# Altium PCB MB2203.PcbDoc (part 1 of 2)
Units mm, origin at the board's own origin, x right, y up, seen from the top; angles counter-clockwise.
Board outline 43 x 31 mm, 4 copper layers (Top Layer, Signal Layer 1, Signal Layer 2, Bottom Layer), stack 0.599 mm thick; 49 components, 37 nets, 166 pads, 723 vias.
Unrouted connection lines stored in the file: 92.
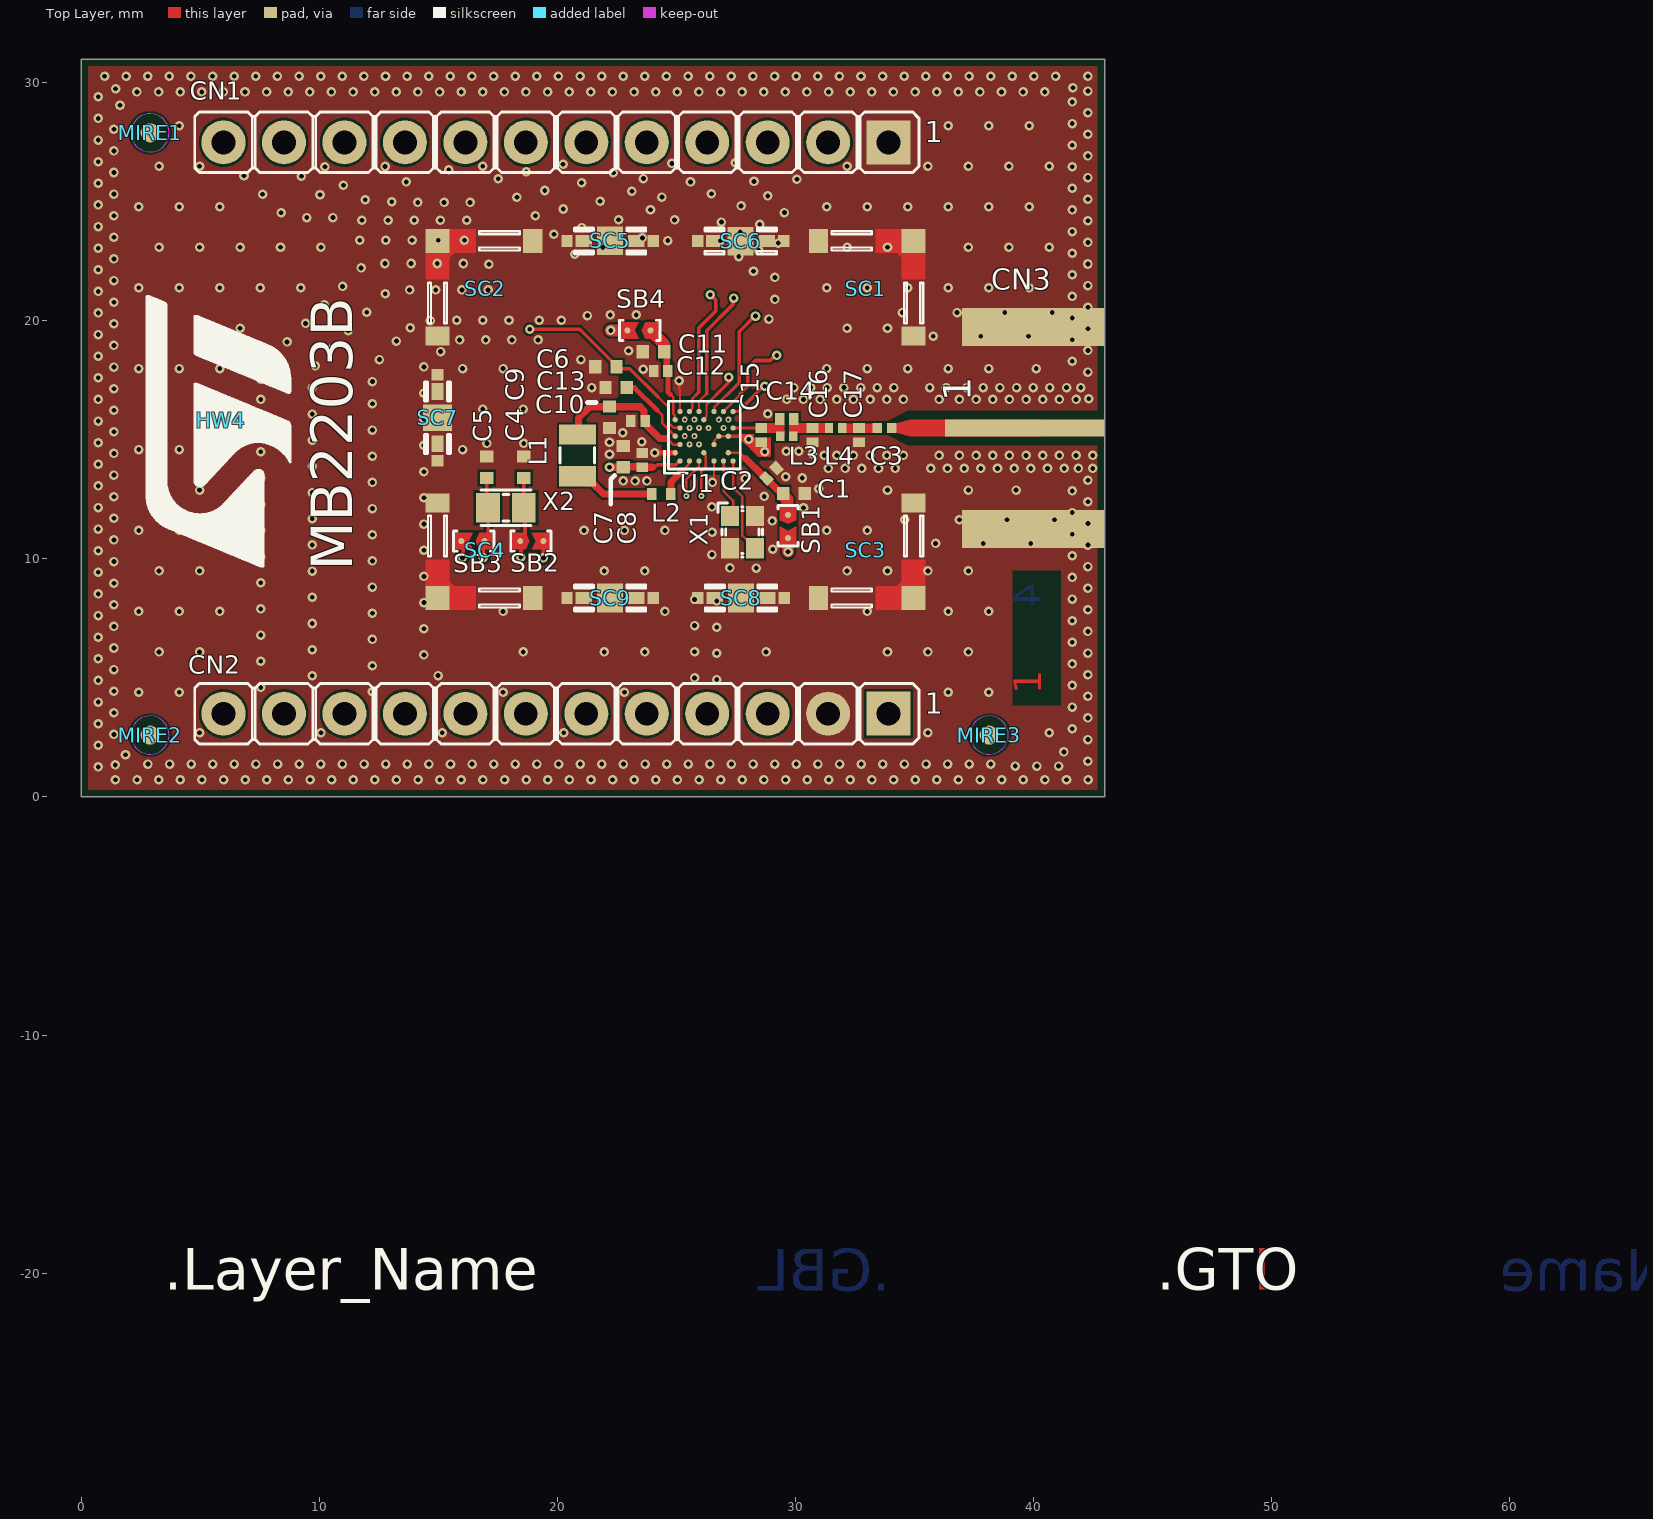
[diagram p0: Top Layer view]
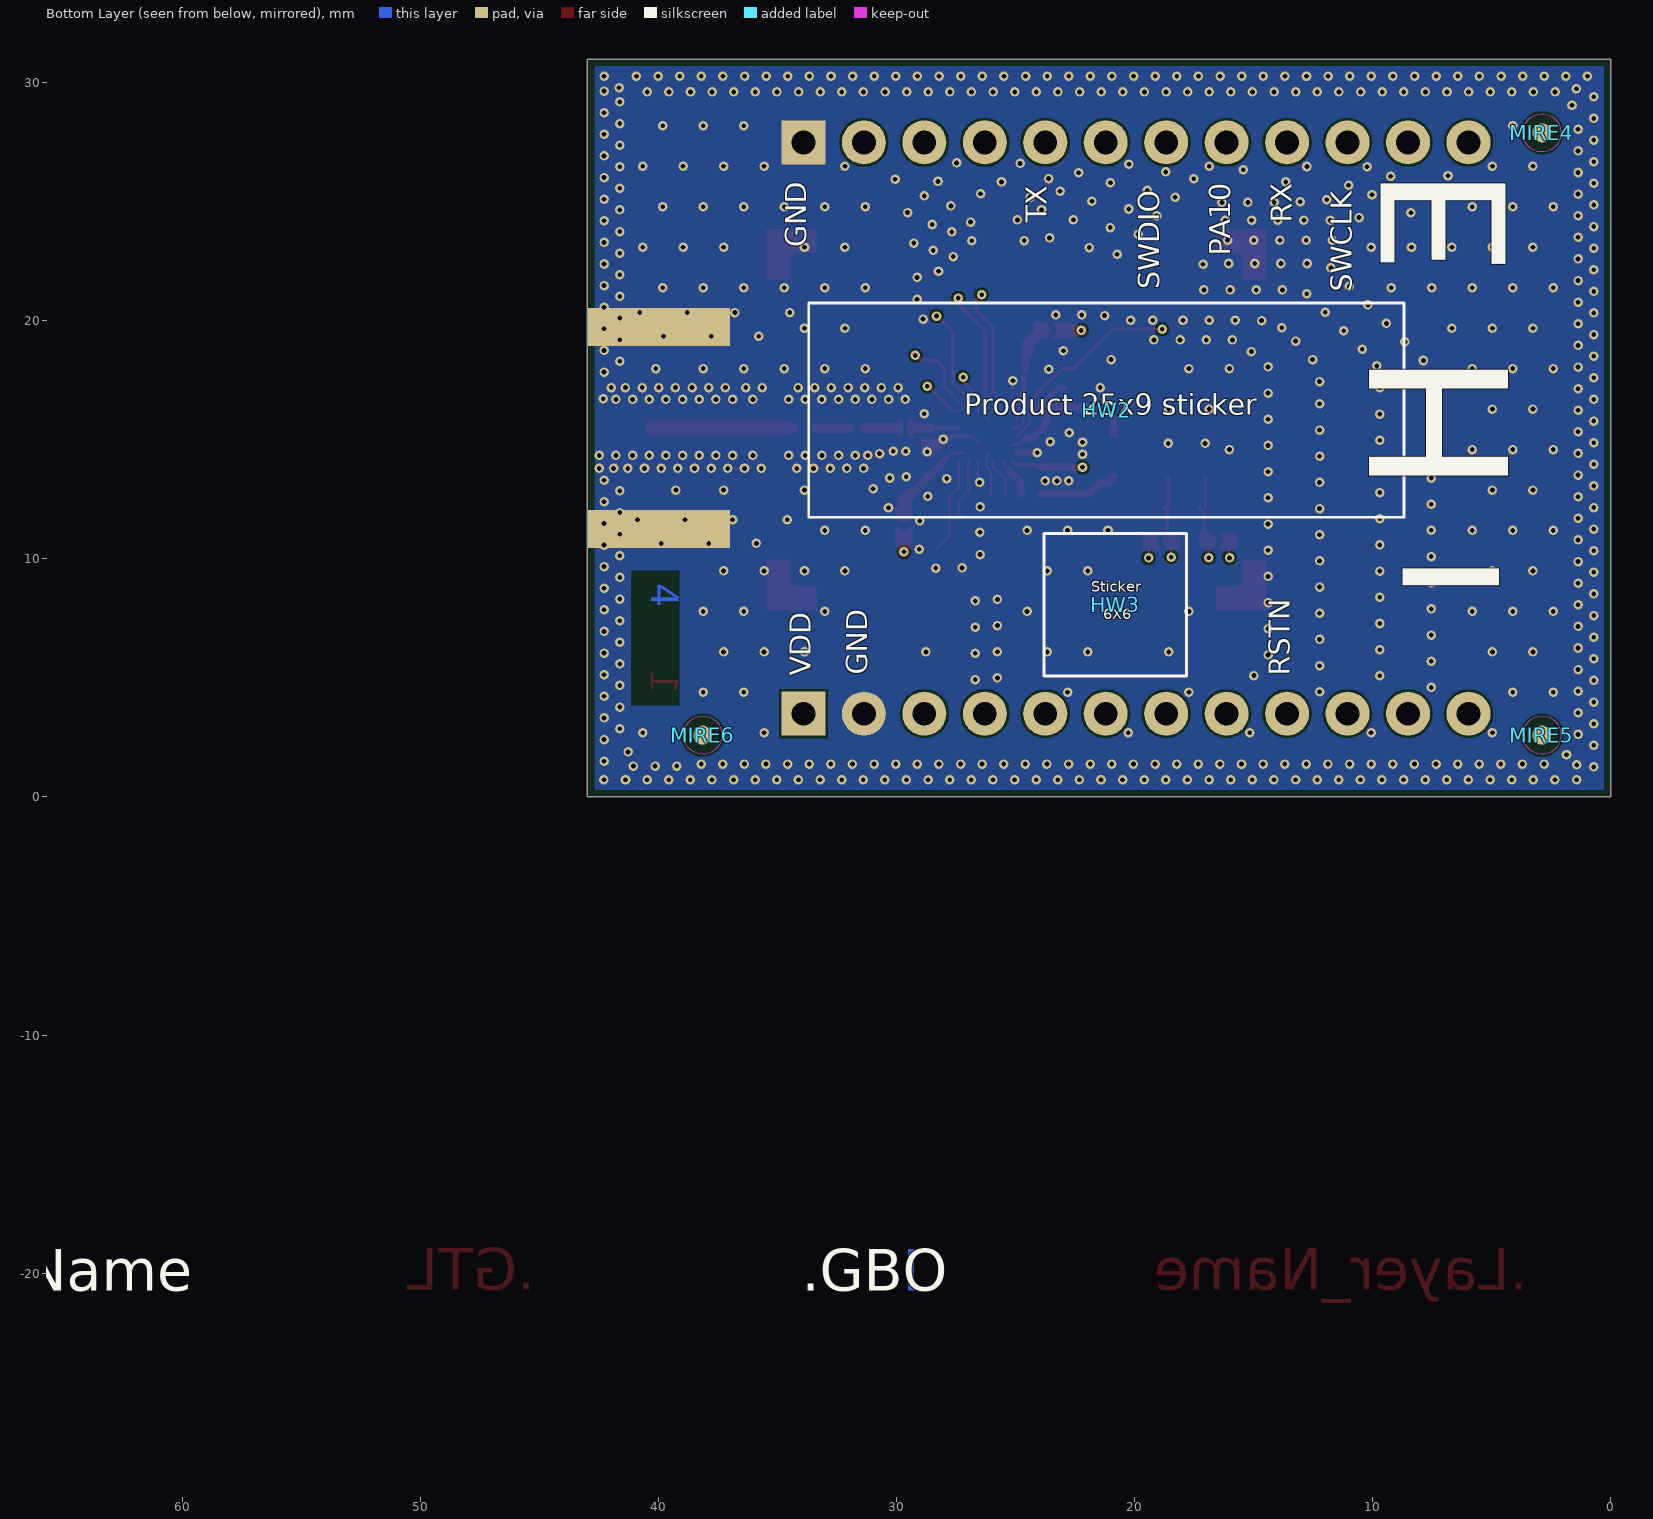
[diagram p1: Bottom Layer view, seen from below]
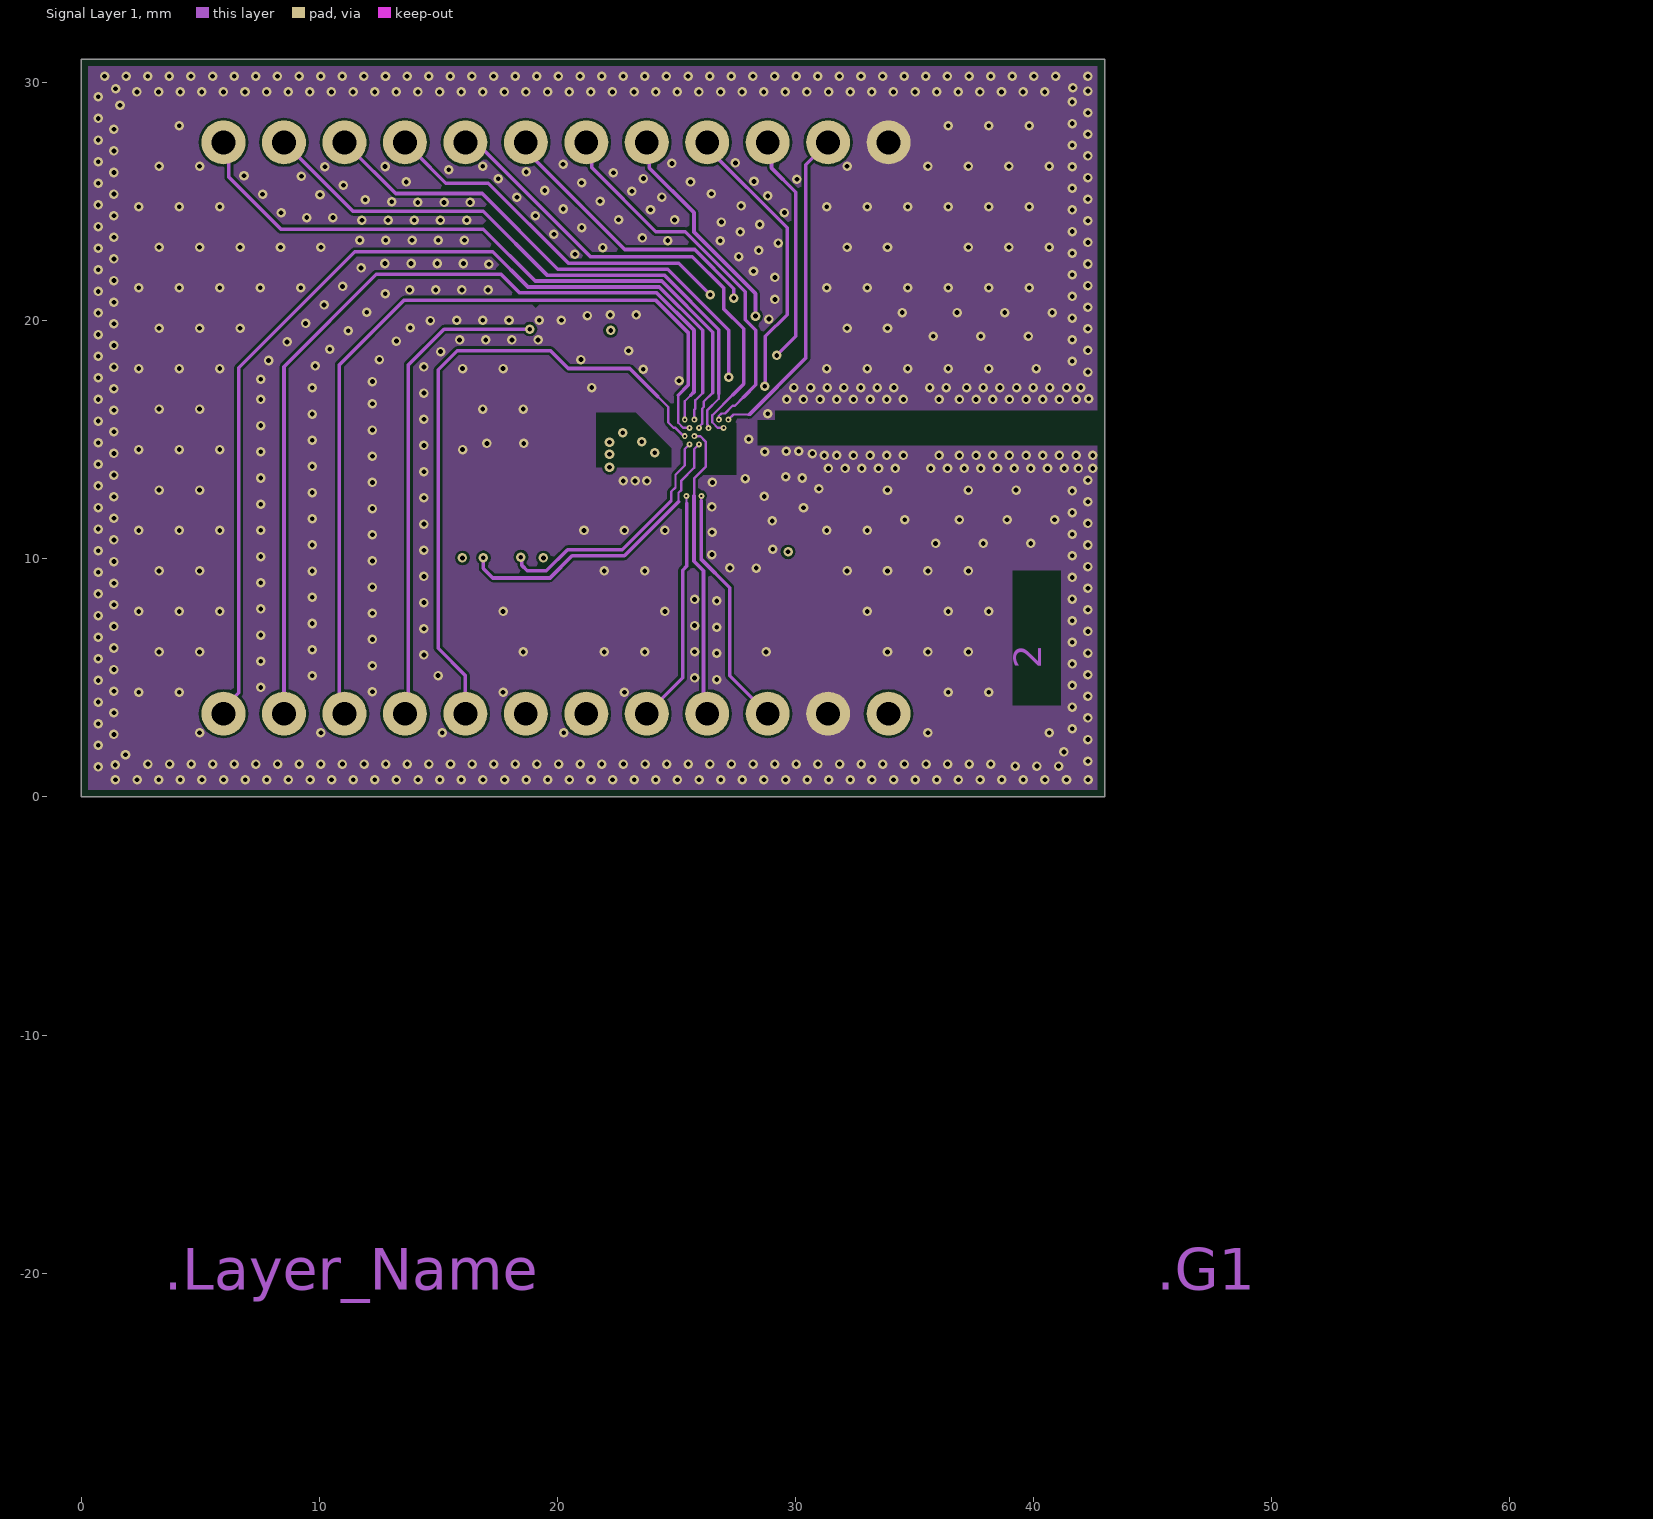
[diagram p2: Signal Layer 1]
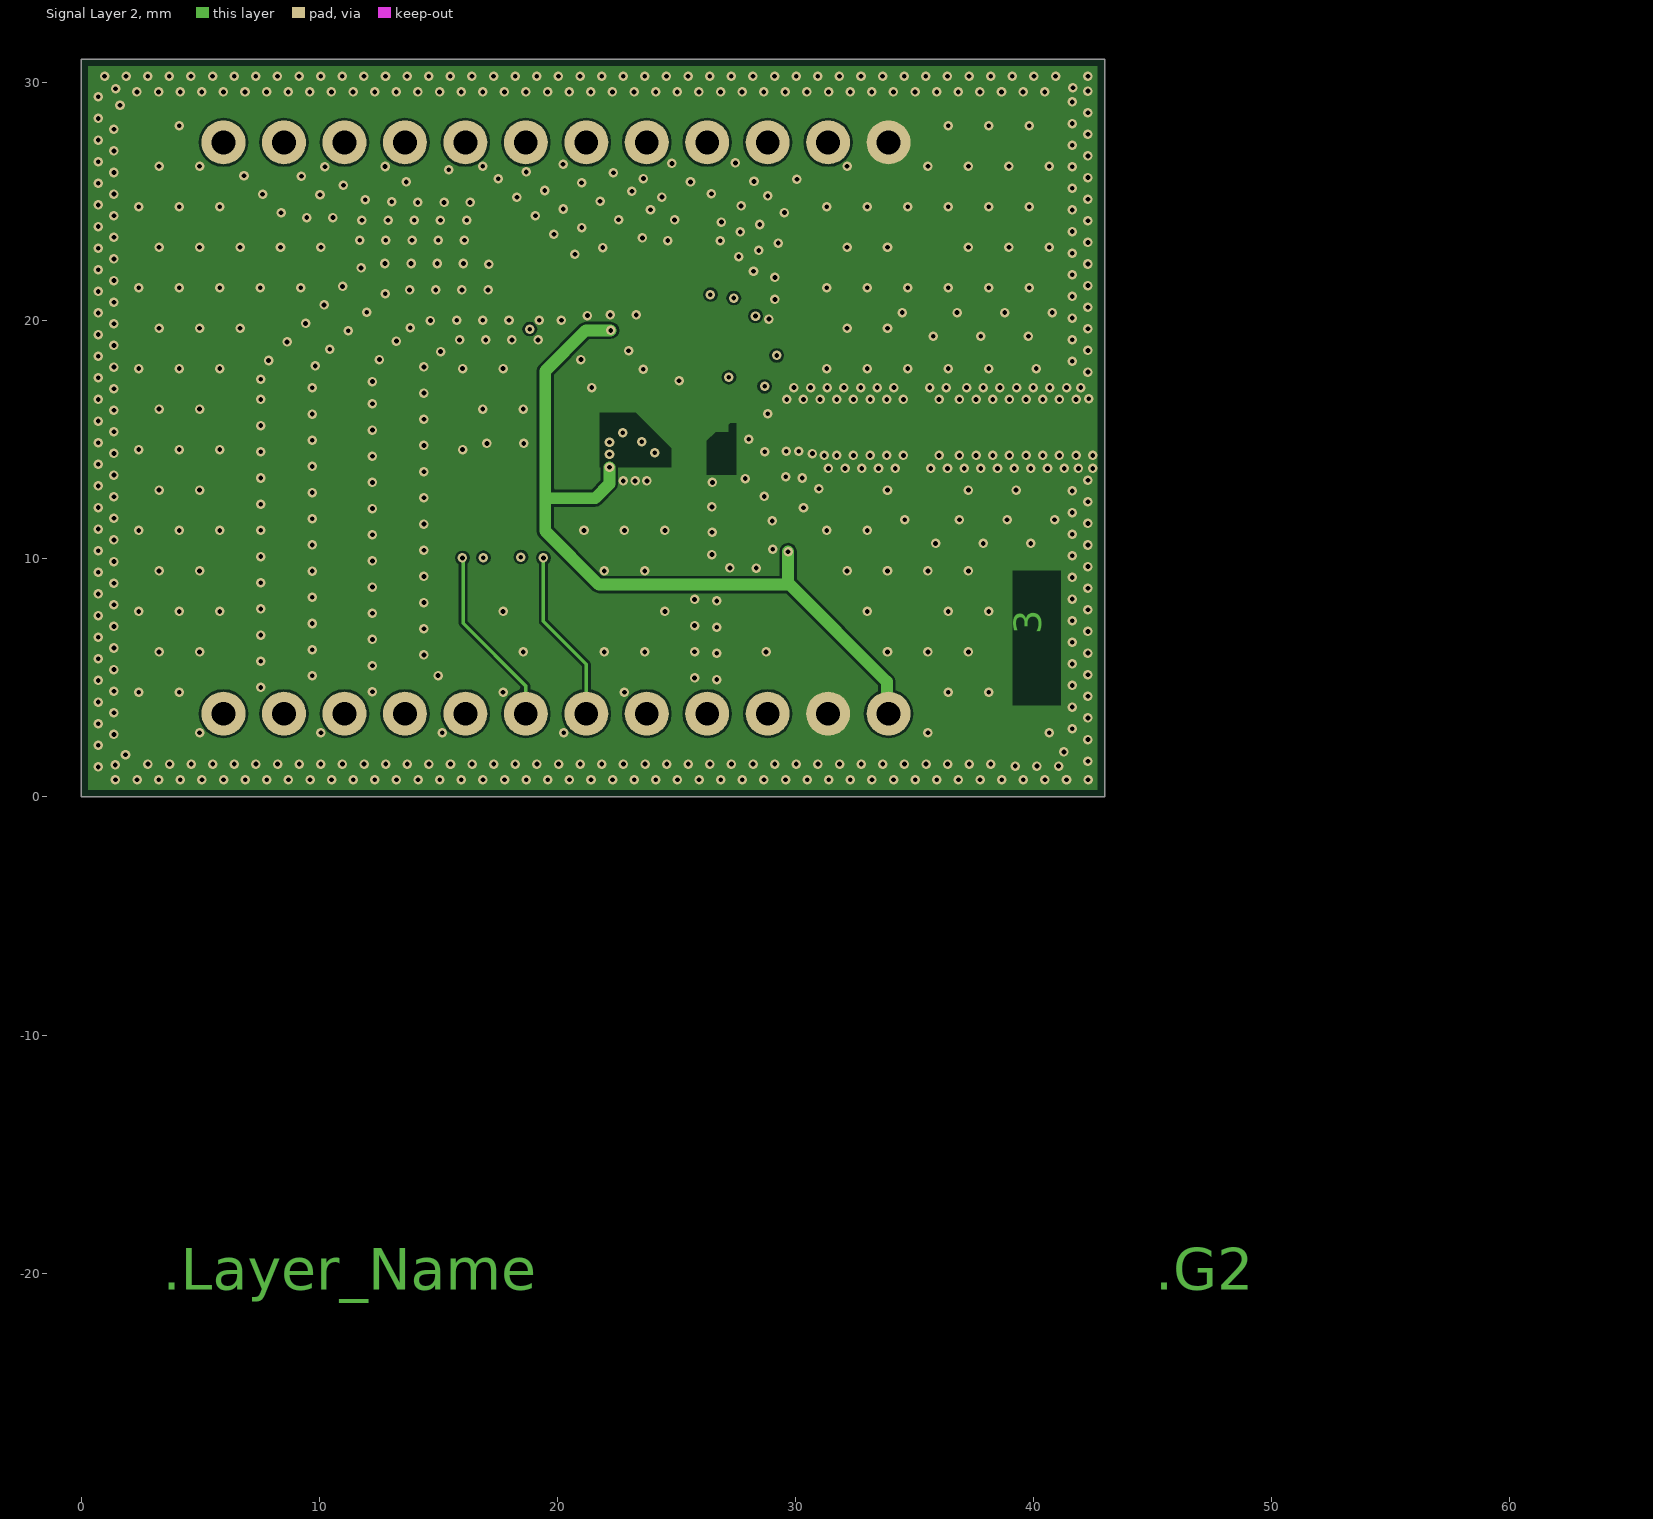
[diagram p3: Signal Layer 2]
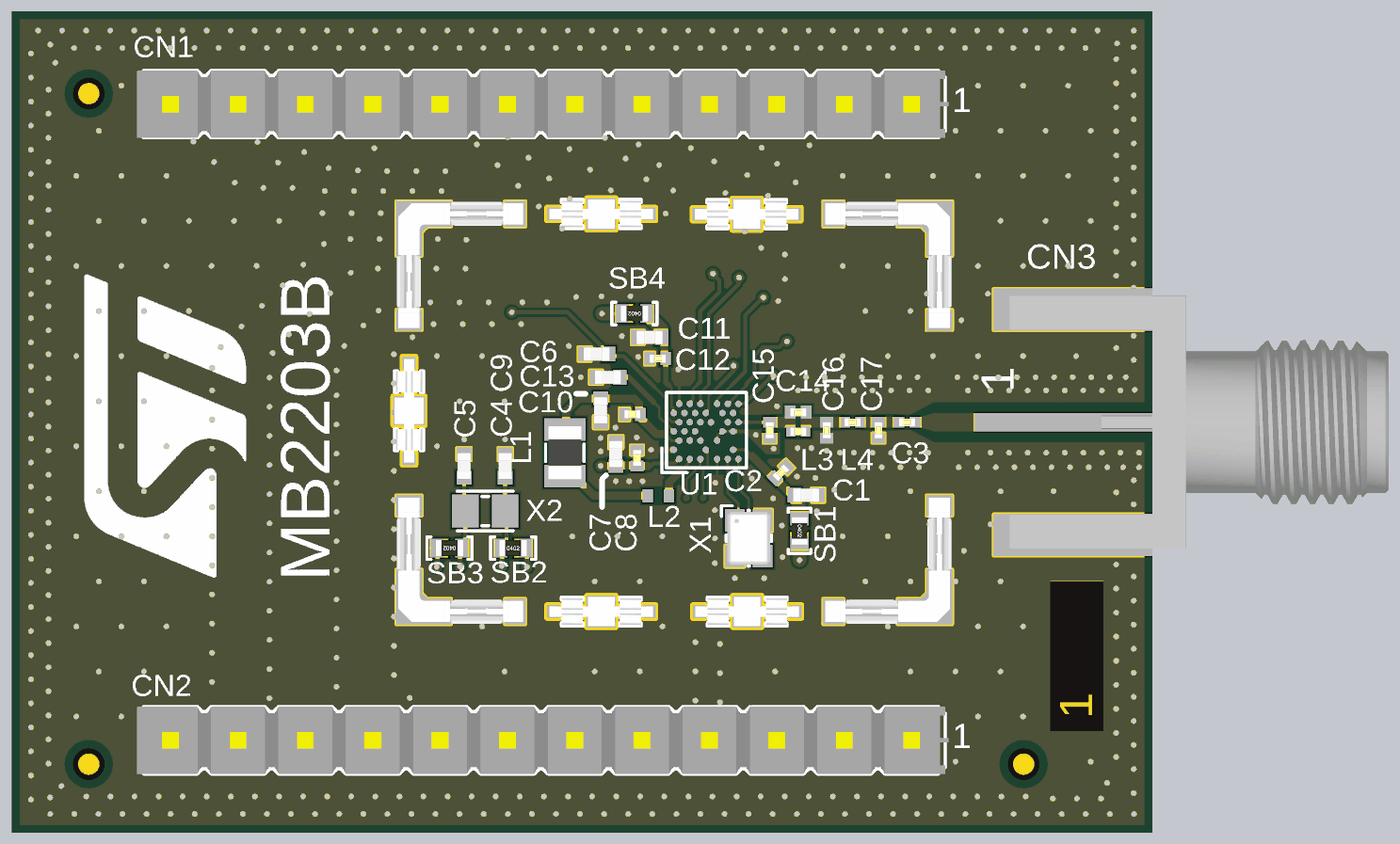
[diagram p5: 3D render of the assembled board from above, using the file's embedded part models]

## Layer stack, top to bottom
Top Solder: solder mask 0.02, Solder Resist, Dk 3.5
Top Layer: signal copper 0.035
Dielectric 1: dielectric 0.102, TU-768 (1x2113), Dk 4.2
Signal Layer 1: signal copper 0.0356
Dielectric2: dielectric 0.254, Tu-768 (2x2113), Dk 4.3
Signal Layer 2: signal copper 0.0356
Dielectric3: dielectric 0.102, TU-768 (1x2113), Dk 4.2
Bottom Layer: signal copper 0.035
Bottom Solder: solder mask 0.02, Solder Resist, Dk 3.5

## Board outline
0,0 0,31 43,31 43,0

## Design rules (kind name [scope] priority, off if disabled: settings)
BoardOutlineClearance [All] p1: gap=0.3 ignorepadtopadclearanceinfootprint=FALSE except(0: Arc-SplitContinuation Track-SplitContinuation SMDPad-SplitContinuation THPad-SplitContinuation Via-SplitContinuation Fill-SplitContinuation Poly-SplitContinuation Region-SplitContinuation Text-SplitContinuation)
Clearance Clearance_RF [InNet('NetC9_2')] p1: gap=0.14 ignorepadtopadclearanceinfootprint=FALSE
Clearance Clearance_RF_1 [InNet('NetC5_1','NetC5_2','NetC9_1')] p2: gap=0.08 ignorepadtopadclearanceinfootprint=FALSE
Clearance [All] p3: gap=0.1 ignorepadtopadclearanceinfootprint=FALSE
HoleToHoleClearance [All] p1: gap=0.15 allowstackedmicrovias=TRUE
MinimumSolderMaskSliver [All] p1: minsoldermaskwidth=0
PlaneClearance [All] p1: clearance=0
PlaneConnect [InNet('GND')] p1: planeconnectstyle=Direct reliefexpansion=0.508 reliefentries=4 reliefconductorwidth=0.254 reliefairgap=0.254
PolygonConnect [InNet('GND')] p1: connectstyle=Direct reliefconductorwidth=0.254 reliefentries=4 polygonreliefangle="90 Angle" airgapwidth=0.254
RoutingVias [All] p1: holewidth=0.2 width=0.4 viastyle="Through Hole" minholewidth=0.2 minwidth=0.4 maxholewidth=0.2 maxwidth=0.4 useviatemplates=TRUE viatemplateguid#1={FA3C43AF-74A2-4DAE-B38C-B4A36A33AEBA} viatemplateguid#2={C3F1866E-02AD-4E07-9877-83EEF2956EBD} viatemplatename#1=v25h10m0 viatemplatename#2=v40h20m0mx0
SMDEntry [All] p1 off: side=TRUE corner=TRUE anyangle=FALSE
SMDNeckDown [All] p1 off: percent=50.000
SMDToCorner [All] p1 off: distance=0
SMDToPlane [All] p1 off: distance=0
SilkToSilkClearance [All] p1: silktosilkclearance=0
SilkToSolderMaskClearance [IsPad] p1: minsilkscreentomaskgap=0 clearancetoexposedcopper=TRUE
SolderMaskExpansion [All] p1: expansion=0.102 istentingtop=FALSE
SupplyNets "Schematic Supply Nets_1" [InNet('VDD')] p1: voltage=0.000
SupplyNets "Schematic Supply Nets" [InNet('GND')] p2: voltage=0.000
ViasUnderSMD [All] p1: allowed=TRUE
Width [All] p1: maxlimit=0.7 minlimit=0.1 preferedwidth=0.1
24 further rules are at their usual default settings.

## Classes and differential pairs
component class Power_Supply: C7 C8 C9 C10 C11 C12 C13 L1 L2 SB4
component class Overview: HW1 HW2 HW3
component class RF_MCU: C1 C2 C3 C4 C5 C6 C14 C15 C16 C17 CN1 CN2 CN3 L3 L4 SB1 SB2 SB3 SC1 SC2 SC3 SC4 SC5 SC6 SC7 SC8 SC9 U1 X1 X2

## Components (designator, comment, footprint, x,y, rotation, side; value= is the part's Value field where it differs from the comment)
C1 "Capacitor" C0402 29.95,12.75 r180 top value=1uF
C2 "Capacitor" C0201_H0P3#1 29,13.6 r225 top value=100nF
C3 "Capacitor" C0201_H0P3#2 33.75,15.5 r0 top value=20pF
C4 "Capacitor" C0402 18.6,13.85 r90 top value=10pF
C5 "Capacitor" C0402 17.05,13.85 r270 top value=10pF
C6 "Capacitor" C0402 22.05,18.075 r180 top value=10nF
C7 "Capacitor" C0402 22.775,14.3 r270 top value=4.7uF
C8 "Capacitor" C0201_H0P3#1 23.575,14.15 r270 top value=100nF
C9 "Capacitor" C0402 22.2,15.95 r90 top value=4.7uF
C10 "Capacitor" C0201_H0P3#1 23.4,15.8 r0 top value=100nF
C11 "Capacitor" C0402 24.05,18.7 r0 top value=1uF
C12 "Capacitor" C0201_H0P3#1 24.35,17.9 r0 top value=100nF
C13 "Capacitor" C0402 22.475,17.2 r0 top value=0.22uF
C14 "Capacitor" C0201_H0P3#3 29.65,15.875 r0 top value=0.3pF
C15 "Capacitor" C0201_H0P3#1 28.575,15.2 r90 top value=0.8pF
C16 "Capacitor" C0201_H0P3#3 30.725,15.2 r90 top value=1.5pF
C17 "Capacitor" C0201_H0P3#1 32.675,15.2 r90 top value=0.8pF
CN1 "Header 12x1" CON_SAMTEC_TSW-112-07-X-S 19.955,27.5 r180 top locked
CN2 "Header 12x1" CON_SAMTEC_TSW-112-07-X-S 19.955,3.5 r180 top locked
CN3 "SMA-J-P-H-ST-EM1" CON_SMA_AMPHENOL_132415 43,15.5 r90 top value=132415
HW2 "STICKER_PRODUCT" STICKER_PRODUCT_25X9 21.2,16.25 r180 bottom value=N/A
HW3 "STICKER_ES" STICKER_ES_6X6 20.825,8.075 r180 bottom value=N/A
HW4 "Logo" LOGO_ST 5.875,15.825 r90 top
L1 "Inductor" IND_0805_MURATA_LQM21 20.85,14.35 r270 top value=10uH
L2 "Inductor" IND_0402_MURATA_LQG15HSXXXX02_H0P5 24.375,12.725 r0 top value=22nH
L3 "Inductor" IND_0201_MURATA_LQP03TN_H0P3 29.65,15.15 r0 top value=2.4nH
L4 "Inductor" IND_0201_MURATA_LQP03TN_H0P3 31.7,15.5 r0 top value=3.3nH
MIRE1 "Comment" MIRE_PLACE_SMD_0P8MM 2.9,27.9 r0 top
MIRE2 "Comment" MIRE_PLACE_SMD_0P8MM 2.9,2.6 r0 top
MIRE3 "Comment" MIRE_PLACE_SMD_0P8MM 38.15,2.6 r0 top
MIRE4 "Comment" MIRE_PLACE_SMD_0P8MM 2.9,27.9 r180 bottom
MIRE5 "Comment" MIRE_PLACE_SMD_0P8MM 2.9,2.6 r180 bottom
MIRE6 "Comment" MIRE_PLACE_SMD_0P8MM 38.15,2.6 r180 bottom
SB1 "SB_ON" SOLDER-BRIDGE_R0402-0R 29.7,11.4 r270 top value=0R
SB2 "SB_ON" SOLDER-BRIDGE_R0402-0R 18.9,10.75 r0 top value=0R
SB3 "SB_ON" SOLDER-BRIDGE_R0402-0R 16.5,10.75 r180 top value=0R
SB4 "SB_ON" SOLDER-BRIDGE_R0402-0R 23.475,19.6 r180 top value=0R
SC1 "Shield-clip_S0951-46R" CLIP_HARWIN_S0981-46R 34.975,23.358 r90 top locked value=S0981-46R
SC2 "Shield-clip_S0951-46R" CLIP_HARWIN_S0981-46R 14.975,23.358 r180 top locked value=S0981-46R
SC3 "Shield-clip_S0951-46R" CLIP_HARWIN_S0981-46R 34.975,8.358 r0 top locked value=S0981-46R
SC4 "Shield-clip_S0951-46R" CLIP_HARWIN_S0981-46R 14.975,8.358 r270 top locked value=S0981-46R
SC5 "Shield-clip_S0951-46R" CLIP_HARWIN_S0951-46R 22.225,23.358 r180 top locked value=S0951-46R
SC6 "Shield-clip_S0951-46R" CLIP_HARWIN_S0951-46R 27.71,23.35 r180 top locked value=S0951-46R
SC7 "Shield-clip_S0951-46R" CLIP_HARWIN_S0951-46R 14.975,15.932 r270 top locked value=S0951-46R
SC8 "Shield-clip_S0951-46R" CLIP_HARWIN_S0951-46R 27.725,8.358 r180 top locked value=S0951-46R
SC9 "Shield-clip_S0951-46R" CLIP_HARWIN_S0951-46R 22.225,8.358 r180 top locked value=S0951-46R
U1 "IC_STM32WB09TEF6TR" ICC_WLCSP36_2P83X2P99_P040 26.187,15.197 r90 top value=STM32WB09TEF6TR
X1 "XTAL_4_PINS" CRY_NX2016SA_4P 27.783,11.125 r270 top value=32MHz
X2 "XTAL_2_PINS" CRY_NX2012SA_2P 17.85,12.15 r180 top value=32.768kHz

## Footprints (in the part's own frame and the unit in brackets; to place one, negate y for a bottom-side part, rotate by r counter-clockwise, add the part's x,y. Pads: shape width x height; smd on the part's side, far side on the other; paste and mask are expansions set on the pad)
C0201_H0P3#1 [mm] "MCD-00699"
  rect 0.4x0.5 smd mask+0.05: 1(-0.3,0) 2(0.3,0)
  body extent -0.32,-0.17 0.32,0.17, height 0.33
C0201_H0P3#2 [mm] "MCD-00699"
  rect 0.4x0.4 smd mask+0.05: 1(-0.3,0) 2(0.3,0)
  body extent -0.32,-0.17 0.32,0.17, height 0.33
C0201_H0P3#3 [mm] "MCD-00699"
  rect 0.4x0.5 smd mask+0: 1(-0.3,0) 2(0.3,0)
  body extent -0.32,-0.17 0.32,0.17, height 0.33
C0402 [mm]
  rect 0.51x0.56 smd mask+0.05: 1(-0.45,0) 2(0.45,0)
  body extent -0.5,-0.3 0.5,0.3, height 0.4
CLIP_HARWIN_S0951-46R [mm] "MCD-01587_CLIP-X1"
  rect 0.48x0.5 smd mask+0.1: 1(-1.81,0) 1(1.81,0)
  rect 0.7x0.5 smd mask+0.1: 1(-1.1,0) 1(1.1,0)
  rect 1.1x1.2 smd mask+0.1: 1(0,0)
  silkscreen extent -1.5,-0.55 1.5,0.55, body extent -2.05,-0.65 2.05,0.65, height 1.28
CLIP_HARWIN_S0981-46R [mm] "MCD-02164"
  rect 0.8x1 smd mask+0.05: 1(-4,0)
  rect 1x0.8 smd mask+0.05: 1(0,4)
  rect 1x1 smd mask+0.05: 1(0,0)
  Top Layer region: -1.6,-0.5 0.5,-0.5 0.5,1.6 -0.5,1.6 -0.5,0.7 -0.7,0.5 -1.6,0.5
  silkscreen extent -3.45,-0.4 0.4,3.45, body extent -4.3,-0.46 0.46,4.3, height 1.4
CON_SAMTEC_TSW-112-07-X-S [mm] "MCD-01795"
  rect 1.85x1.85 / inner round 1.85 / far side rect 1.85x1.85 hole 1 mask+0.05: 1(-13.97,0)
  round 1.85 hole 1 mask+0.05: 2(-11.43,0) 3(-8.89,0) 4(-6.35,0) 5(-3.81,0) 6(-1.27,0) 7(1.27,0) 8(3.81,0) 9(6.35,0) 10(8.89,0) 11(11.43,0) 12(13.97,0)
  silkscreen extent -15.24,-1.27 15.18,1.27, body extent -15.37,-1.27 15.24,1.27, height 8.38
CON_SMA_AMPHENOL_132415 [mm] "MCD-04961"
  rect 0.7x6.7 smd mask+0.05: 1(0,3.35)
  rect 1.6x6 smd mask+0.05: 2(-4.25,3) 3(4.25,3)
  rect 1.6x6 smd far side mask+0.05: 4(4.25,3) 5(-4.25,3)
  body extent -4.76,-8.89 4.76,5.38, height 4.08
CRY_NX2012SA_2P [mm]
  rect 1x1.25 smd mask+0.05: 1(-0.75,0) 2(0.75,0)
  silkscreen extent -1.05,-0.75 1.05,0.75, body extent -1.05,-0.63 1.05,0.63, height 0.6
CRY_NX2016SA_4P [mm]
  rect 0.85x0.75 smd mask+0.05: 1(-0.675,-0.525) 2(0.675,-0.525) 3(0.675,0.525) 4(-0.675,0.525)
  silkscreen extent -1.22,-1.02 1.05,0.85, body extent -1.05,-0.85 1.05,0.85, height 0.7
ICC_WLCSP36_2P83X2P99_P040 [mm] "MCD-04889"
  round 0.225 smd paste+0.012 mask+0.032: A2(-0.736,1.226) A4(-0.043,1.226) A6(0.65,1.226) B1(-1.082,1.026) B3(-0.389,1.026) B5(0.304,1.026) B7(0.996,1.026) C4(-0.043,0.826) C6(0.65,0.826) D1(-1.082,0.626) D3(-0.389,0.626) D5(0.303,0.626) D7(0.996,0.626) E4(-0.043,0.426) E6(0.65,0.426) F1(-1.082,0.226) F3(-0.389,0.226) F5(0.303,0.226) F7(0.996,0.226) G2(-0.736,0.025) G6(0.65,0.025) H5(0.303,-0.175) J1(-1.082,-0.404) J3(-0.389,-0.404) J7(0.996,-0.404) K4(-0.043,-0.605) K6(0.65,-0.605) L1(-1.082,-0.805) L5(0.303,-0.805) L7(0.996,-0.805) M2(-0.736,-1.005) M4(-0.043,-1.005) M6(0.65,-1.005) N1(-1.083,-1.205) N5(0.303,-1.205) N7(0.996,-1.205)
  silkscreen extent -1.6,-1.51 1.43,1.68, body extent -1.43,-1.51 1.43,1.51, height 0.44
IND_0201_MURATA_LQP03TN_H0P3 [mm] "MCD-02439"
  rect 0.35x0.4 smd mask+0.05: 1(-0.275,0) 2(0.275,0)
  body extent -0.32,-0.17 0.32,0.17, height 0.33
IND_0402_MURATA_LQG15HSXXXX02_H0P5 [mm] "MCD-03474"
  rect 0.4x0.5 smd mask+0.05: 1(-0.4,0) 2(0.4,0)
  body extent -0.55,-0.28 0.55,0.28, height 0.55
IND_0805_MURATA_LQM21 [mm] "MCD-02317"
  rect 0.85x1.55 smd mask+0.05: 1(-0.875,0) 2(0.875,0)
  silkscreen extent -0.33,-0.72 0.33,0.72, body extent -1.1,-0.72 1.1,0.72, height 1.45
LOGO_ST [mm]
  silkscreen extent -6.18,-2.95 5.25,3.14
MIRE_PLACE_SMD_0P8MM [mm]
  round 0.8 smd paste-10 mask+0.2: 1(0,0)
  Top Layer keep-out circle w0.01: c0,0 r0.804
SOLDER-BRIDGE_R0402-0R [mil] "MCD-01619"
  round 10 smd paste-393.7: 1(-17.72,0) 2(20.67,0)
  Top Layer region: -30.51,-13.78 -30.51,13.78 -8.86,13.78 -2.95,0 -8.86,-13.78
  Top Layer region: 1.48,13.78 8.37,0 1.48,-13.78 30.51,-13.78 30.51,13.78
  silkscreen extent -33,-17 33,17, body extent -20,-12 20,12, height 14
STICKER_ES_6X6 [mm] "Sticker to mention board QR code 8X8"
  silkscreen extent -3,-3 3,3
STICKER_PRODUCT_25X9 [mm] "Sticker to mention board CPN code"
  silkscreen extent -12.5,-4.5 12.5,4.5

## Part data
C1 C11: library part MCD-03432, "Capacitor, MLCC, 1uF, X7R, 6.3V,+/- 10%, 0402, T=0.5mm", Manufacturer=MURATA, Manufacturer_Part_Number=GRM155R70J105KA12, Package=0402
C2 C8 C10 C12: library part MCD-01535, "Capacitor, MLCC,100nF, 10V, X5R, +/-10%, 0201, T=0.3mm", Manufacturer=MURATA, Manufacturer_Part_Number=GRM033R61A104KE15, Package=0201
C3: library part MCD-03543, "Capacitor, MLCC, 20pF, 25V, COG, +/-2%, 0201, T=0.3mm", Manufacturer=MURATA, Manufacturer_Part_Number=GJM0335C1E200GB01, Package=0201
C4 C5: library part MCD-00015, "Capacitor, MLCC, 10pF, 50V, NPO, +/-5%, 0402, T=0.5mm", Manufacturer=YAGEO, Manufacturer_Part_Number=CC0402JRNPO9BN100, Package=0402
C6: library part MCD-00011, "Capacitor, MLCC, 10nF, 16V, X7R, +/-10%, 0402, T=0.5mm", Manufacturer=YAGEO, Manufacturer_Part_Number=CC0402KRX7R7BB103, Package=0402
C7 C9: library part MCD-03431, "Capacitor, MLCC, 4.7uF, X5R, 10V, +/-20%, 0402, T=0.5mm", Manufacturer=MURATA, Manufacturer_Part_Number=GRM155R61A475MEAAD, Package=0402
C13: library part MCD-03483, "Capacitor, MLCC, 0.22uF, X5R, 6.3V, +/-10%, 0402, T=0.5mm", Manufacturer=YAGEO, Manufacturer_Part_Number=CC0402KRX5R5BB224, Package=0402
C14: library part MCD-04945, "Capacitor, MLCC, 0.3pF, 25V, COG, +/-0.05pF, 0201, T=0.3mm", Manufacturer=MURATA, Manufacturer_Part_Number=GJM0335C1ER30WB01D
C15 C17: library part MCD-04946, "Capacitor, MLCC, 0.8pF, 25V, +/- 0.05pF, C0G (NP0), 0201", Manufacturer=MURATA, Manufacturer_Part_Number=GJM0335C1ER80WB01D
C16: library part MCD-04947, "Capacitor, MLCC, 1.5pF, 25V, COG, +/-0.1pF, 0201", Manufacturer=MURATA, Manufacturer_Part_Number=GJM0335C1E1R5BB01D
CN1 CN2: library part MCD-01795, "Header, 12x1, 2.54mm, VR, TH, T=5.84mm/2.54mm", Manufacturer=SAMTEC, Manufacturer_Part_Number=TSW-112-07-T-S
CN3: library part MCD-04961, "Jack_SMA, VR, PCB edge, 50R, T=7.92mm", Manufacturer=AMPHENOL, Manufacturer_Part_Number=132415
HW2: library part MCD-00547, "Sticker product, 25x9mm", Manufacturer=N/A, Manufacturer_HQ_COO=Unknown
HW3: library part MCD-00234, "Sticker ES, 6x6mm", Manufacturer=N/A
HW4: library part MCD-00625, "\"STMicroelectronics\" logo footprint for PCB"
L1: library part MCD-03438, "Inductor, MLCC, 10uH, +/-20%, 300mA, 845mR, 0805, T=1.45mm", Manufacturer=MURATA, Manufacturer_Part_Number=LQM21DN100M70L, Package=0805
L2: library part MCD-03439, "Inductor, MLCC, 22nH, +/-2%, 350mA, 0.58R, 0402, T=1.45mm", Manufacturer=MURATA, Manufacturer_Part_Number=LQW15AN22NG00, Package=0402
L3: library part MCD-04955, "Inductor, 2.4nH, +/-0.1nH, 500mA, 200mR, 0201, T=0.33mm", Manufacturer=MURATA, Manufacturer_Part_Number=LQP03TN2N4B02D
L4: library part MCD-02439, "Inductor, 3.3nH, +/-0.1nH, 450mA, 250mR, 0201, T=0.33mm", Manufacturer=MURATA, Manufacturer_Part_Number=LQP03TN3N3B02D, Package=0201
SB1 SB2 SB3 SB4: library part MCD-01618, "Resistor, 0R, SB0402, 5%, 0.063W", Manufacturer=YAGEO, Manufacturer_Part_Number=RC0402JR-070RL, Package=0402
SC1 SC2 SC3 SC4: library part MCD-02164, "Shield clip Harwin S0981-46R to fix RF shielded cavity", Manufacturer=HARWIN, Manufacturer_Part_Number=S0981-46R, Package=0.8x4.7x1.4mm
SC5 SC6 SC7 SC8 SC9: library part MCD-01587, "RFI shield clip mini TIN SMD", Manufacturer=HARWIN, Manufacturer_Part_Number=S0951-46R, Package=1.1x3.9mm
U1: library part MCD-04889, "MCU, ARM Cortex-M0+ 32-bit, 512KB Flash, 64KB RAM, With Crypto", Manufacturer=STMICROELECTRONICS, Manufacturer_Part_Number=STM32WB09TEF6TR, Package=WLCSP36
X1: library part MCD-01446, "Crystal, 32MHz, 8pF, +/-10ppm, 60R, 2x1.6mm", Manufacturer=NDK, Manufacturer_Part_Number=NX2016SA-32MHZ-EXS00A-CS06654, Package=2x1.6mm
X2: library part MCD-01445, "Crystal, 32.768kHz, 7pF, +/-20ppm, 80K, 2.05x1.2mm", Manufacturer=NDK, Manufacturer_Part_Number=NX2012SA-32.768KHZ-EXS00A-MU00389, Package=2.05x1.2mm

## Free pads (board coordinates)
  round 0.508 on Mech16: 1(15.17,-27.648) 1(64.017,-27.648)

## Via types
v1: diameter 0.4, hole 0.2, Top Layer to Bottom Layer, tented both sides, 709 vias
v2: diameter 0.25, hole 0.1, Top Layer to Signal Layer 1, tented both sides, 14 vias

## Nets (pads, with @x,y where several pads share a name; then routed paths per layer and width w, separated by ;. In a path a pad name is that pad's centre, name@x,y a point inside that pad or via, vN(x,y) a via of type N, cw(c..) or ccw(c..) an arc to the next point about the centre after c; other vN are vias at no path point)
GND: C1.1 C2.1 C4.2 C5.1 C6.2 C7.1 C8.1 C9.1 C10.1 C11.1 C12.1 C13.1 C15.1 C16.1 C17.1 CN1.1 CN2.2 CN3.2 CN3.3 CN3.4 CN3.5 SC1.1 SC2.1 SC3.1 SC4.1 SC5.1 SC6.1 SC7.1 SC8.1 SC9.1 U1.A2 U1.B7 U1.J1 U1.J3 U1.K4 U1.M4 X1.2 X1.4 | length 4.8
  Top Layer w0.1: v1(25.125,17.485) 25.125,17.153 25.162,17.116 U1.B7@25.161,16.193 ; v1(26.524,13.214) 26.524,13.295 26.592,13.364 U1.J1@26.592,14.12 ; U1.J3@26.592,14.813 26.592,14.96 26.792,15.16 U1.M4@27.192,15.16
  Top Layer w0.148: U1.M4@27.197,15.158 v1@28.07,15.158
  Top Layer w0.25: v1(24.1,14.461) 24.5,14.461 ; 24.523,14.461 U1.A2@24.962,14.461
  other v1: 1.447,0.72 2.355,0.72 3.263,0.72 4.171,0.72 5.079,0.72 5.987,0.72 6.895,0.72 7.803,0.72 8.711,0.72 9.619,0.72 10.527,0.72 11.435,0.72 12.343,0.72 13.251,0.72 14.159,0.72 15.067,0.72 15.975,0.72 16.883,0.72 17.791,0.72 18.699,0.72 19.607,0.72 20.515,0.72 21.423,0.72 22.331,0.72 23.239,0.72 24.147,0.72 25.055,0.72 25.963,0.72 26.871,0.72 27.779,0.72 28.687,0.72 29.595,0.72 30.503,0.72 31.411,0.72 32.319,0.72 33.227,0.72 34.135,0.72 35.043,0.72 35.951,0.72 36.859,0.72 37.767,0.72 38.675,0.72 39.583,0.72 40.491,0.72 41.399,0.72 42.307,0.72 0.72,1.264 39.25,1.3 40.158,1.3 41.066,1.3 1.441,1.347 2.809,1.38 3.717,1.38 4.625,1.38 5.533,1.38 6.441,1.38 7.349,1.38 8.257,1.38 9.165,1.38 10.073,1.38 10.981,1.38 11.889,1.38 12.797,1.38 13.705,1.38 14.613,1.38 15.521,1.38 16.429,1.38 17.337,1.38 18.245,1.38 19.153,1.38 20.061,1.38 20.969,1.38 21.877,1.38 22.785,1.38 23.693,1.38 24.601,1.38 25.509,1.38 26.417,1.38 27.325,1.38 28.233,1.38 29.141,1.38 30.049,1.38 30.957,1.38 31.865,1.38 32.773,1.38 33.681,1.38 34.589,1.38 35.497,1.38 36.405,1.38 37.313,1.38 38.221,1.38 42.3,1.505 1.867,1.776 41.293,1.894 0.72,2.172 42.3,2.413 1.38,2.626 4.979,2.695 10.079,2.695 15.179,2.695 20.279,2.695 35.579,2.695 40.679,2.695 41.64,2.867 0.72,3.08 42.3,3.321 1.38,3.534 41.64,3.775 0.72,3.988 42.3,4.229 2.429,4.395 4.129,4.395 17.729,4.395 22.829,4.395 36.429,4.395 38.129,4.395 12.239,4.416 1.38,4.442 7.55,4.6 41.64,4.683 0.72,4.896 26.702,4.933 25.775,5 9.714,5.087 15,5.1 42.3,5.137 1.38,5.35 12.239,5.516 41.64,5.591 7.55,5.7 0.72,5.804 14.403,5.965 26.702,6.033 42.3,6.045 3.279,6.095 4.979,6.095 18.579,6.095 21.979,6.095 23.679,6.095 25.775,6.1 28.779,6.095 33.879,6.095 35.579,6.095 37.279,6.095 9.714,6.187 1.38,6.258 41.64,6.499 12.239,6.616 0.72,6.712 7.55,6.8 42.3,6.953 14.403,7.065 26.702,7.133 1.38,7.166 25.775,7.2 9.714,7.287 41.64,7.407 0.72,7.62 12.239,7.716 2.429,7.795 4.129,7.795 5.829,7.795 17.729,7.795 24.529,7.795 33.029,7.795 36.429,7.795 38.129,7.795 42.3,7.861 7.55,7.9 1.38,8.074 14.403,8.165 26.702,8.233 25.775,8.3 41.64,8.315 9.714,8.387 0.72,8.528 42.3,8.769 12.239,8.816 1.38,8.982 7.55,9 41.64,9.223 14.403,9.265 0.72,9.436 3.279,9.495 4.979,9.495 9.714,9.487 21.979,9.495 23.679,9.495 32.179,9.495 33.879,9.495 35.579,9.495 37.279,9.495 27.259,9.62 28.369,9.614 42.3,9.677 1.38,9.89 12.239,9.916 7.55,10.1 41.64,10.131 26.504,10.185 0.72,10.344 14.403,10.365 29.056,10.408 9.714,10.587 42.3,10.585 35.9,10.65 37.9,10.65 39.9,10.65 1.38,10.798 12.239,11.016 41.64,11.039 26.51,11.12 2.429,11.195 4.129,11.195 5.829,11.195 7.55,11.2 21.129,11.195 22.829,11.195 24.529,11.195 31.329,11.195 33.029,11.195 0.72,11.252 14.403,11.465 42.3,11.493 29.034,11.599 34.6,11.65 36.9,11.65 38.9,11.65 40.9,11.65 9.714,11.687 1.38,11.706 41.64,11.947 12.239,12.116 0.72,12.16 30.35,12.15 26.505,12.185 7.55,12.3 42.3,12.401 14.403,12.565 1.38,12.614 28.7,12.625 9.714,12.787 41.64,12.855 3.279,12.895 4.979,12.895 33.879,12.895 37.279,12.895 39.279,12.895 31,12.95 0.72,13.068 12.239,13.216 22.775,13.275 23.275,13.275 23.775,13.275 42.3,13.309 27.898,13.373 7.55,13.4 30.3,13.4 29.6,13.45 1.38,13.522 14.403,13.665 31.398,13.8 32.099,13.8 32.8,13.8 33.501,13.8 34.201,13.8 35.7,13.8 36.4,13.8 37.101,13.8 37.801,13.8 38.5,13.8 39.2,13.8 39.901,13.8 40.601,13.8 41.3,13.8 41.9,13.8 42.5,13.8 9.714,13.887 0.72,13.976 12.239,14.316 31.225,14.35 31.749,14.35 32.449,14.35 33.148,14.35 33.848,14.35 34.548,14.35 36.047,14.35 36.9,14.35 37.6,14.35 38.3,14.35 39,14.35 39.7,14.35 40.4,14.35 41.1,14.35 41.8,14.35 42.5,14.35 22.2,14.4 1.38,14.43 30.725,14.425 7.55,14.5 28.725,14.5 29.626,14.525 30.15,14.525 2.429,14.595 4.129,14.595 5.829,14.595 16.029,14.595 14.403,14.765 17.05,14.85 18.6,14.85 0.72,14.884 22.2,14.9 23.56,14.925 9.714,14.987 28.05,15.025 22.76,15.3 1.38,15.338 12.239,15.416 7.55,15.6 0.72,15.792 14.403,15.865 9.714,16.087 28.85,16.1 1.38,16.246 3.279,16.295 4.979,16.295 16.879,16.295 18.579,16.295 12.239,16.516 0.72,16.7 7.55,16.7 29.646,16.7 30.347,16.7 31.048,16.7 31.749,16.7 32.45,16.7 33.15,16.7 33.849,16.7 34.549,16.7 36.045,16.7 36.9,16.7 37.6,16.7 38.3,16.7 39,16.7 39.7,16.7 40.4,16.7 41.1,16.7 41.8,16.7 42.338,16.727 14.403,16.965 1.38,17.154 9.714,17.187 21.45,17.2 29.947,17.2 30.648,17.2 31.349,17.2 32.05,17.2 32.751,17.2 33.451,17.2 34.15,17.2 35.65,17.2 36.349,17.2 37.199,17.2 37.899,17.2 38.6,17.2 39.299,17.2 39.999,17.2 40.699,17.2 41.4,17.2 42,17.2 12.239,17.45 7.55,17.55 0.72,17.608 42.3,17.849 23.615,17.965 2.429,17.995 4.129,17.995 5.829,17.995 16.029,17.995 17.729,17.995 31.329,17.995 33.029,17.995 34.729,17.995 36.429,17.995 38.129,17.995 40.129,17.995 1.38,18.062 14.403,18.065 9.834,18.11 41.64,18.303 7.877,18.336 12.534,18.375 21,18.375 0.72,18.516 15.103,18.71 23,18.75 42.3,18.757 10.448,18.806 1.38,18.97 8.655,19.114 13.25,19.15 15.9,19.2 17,19.2 18.1,19.2 19.2,19.2 41.64,19.211 35.8,19.35 37.8,19.35 39.8,19.35 0.72,19.424 11.225,19.584 42.3,19.665 3.279,19.695 4.979,19.695 6.679,19.695 13.829,19.711 32.179,19.695 33.879,19.695 1.38,19.878 9.433,19.891 14.679,20.011 15.779,20.025 16.879,20.025 17.979,20.025 19.25,20.025 20.179,20.025 28.9,20.075 41.64,20.119 21.275,20.225 22.229,20.25 23.325,20.25 0.72,20.332 34.5,20.35 36.8,20.35 38.8,20.35 40.8,20.35 12.003,20.362 42.3,20.573 10.211,20.669 1.38,20.786 29.15,20.9 41.64,21.027 12.781,21.139 0.72,21.24 13.8,21.3 14.9,21.3 16,21.3 17.1,21.3 2.429,21.395 4.129,21.395 5.829,21.395 7.529,21.395 9.229,21.395 31.329,21.395 33.029,21.395 34.729,21.395 36.429,21.395 38.129,21.395 39.829,21.395 10.989,21.447 42.3,21.481 1.38,21.694 29.15,21.825 41.64,21.935 28.249,22.082 0.72,22.148 11.766,22.225 17.137,22.382 42.3,22.389 12.766,22.411 13.866,22.411 14.966,22.411 16.066,22.411 1.38,22.602 27.631,22.699 20.75,22.8 41.64,22.843 28.471,22.959 0.72,23.056 3.279,23.095 4.979,23.095 6.679,23.095 8.379,23.095 10.079,23.095 21.92,23.08 32.179,23.095 33.879,23.095 37.279,23.095 38.979,23.095 40.679,23.095 29.288,23.271 42.3,23.297 24.65,23.375 26.853,23.371 11.705,23.389 12.805,23.389 13.905,23.389 15.005,23.389 16.105,23.389 23.582,23.487 1.38,23.51 19.865,23.642 27.693,23.737 41.64,23.751 21.035,23.922 0.72,23.964 28.51,24.049 26.9,24.15 42.3,24.205 11.8,24.225 12.9,24.225 14,24.225 15.1,24.225 16.2,24.225 24.935,24.239 22.581,24.25 9.483,24.339 10.583,24.339 1.38,24.418 19.087,24.42 8.402,24.54 29.55,24.55 23.923,24.669 41.64,24.659 20.257,24.7 2.429,24.795 4.129,24.795 5.829,24.795 31.329,24.795 33.029,24.795 34.729,24.795 36.429,24.795 38.129,24.795 39.829,24.795 27.729,24.829 0.72,24.872 14.15,24.975 15.25,24.975 16.345,24.975 13.05,25 21.803,25.028 11.942,25.089 42.3,25.113 18.309,25.198 24.405,25.203 28.85,25.25 10.039,25.295 1.38,25.326 7.624,25.318 26.483,25.339 23.145,25.447 19.479,25.478 41.64,25.567 11.023,25.693 0.72,25.78 21.025,25.806 13.661,25.839 25.603,25.839 28.271,25.859 30.075,25.947 17.531,25.976 23.628,25.981 42.3,26.021 9.261,26.073 6.846,26.095 1.38,26.234 22.367,26.225 18.701,26.256 15.45,26.346 10.245,26.471 3.279,26.495 4.979,26.495 12.771,26.485 16.879,26.495 32.179,26.495 35.579,26.495 37.279,26.495 38.979,26.495 40.679,26.495 41.64,26.475 20.248,26.584 24.825,26.616 27.493,26.637 0.72,26.688 42.3,26.929 1.38,27.142 41.64,27.383 0.72,27.596 42.3,27.837 1.38,28.05 4.129,28.195 36.429,28.195 38.129,28.195 39.829,28.195 41.64,28.291 0.72,28.504 42.3,28.745 1.637,29.062 41.64,29.199 0.72,29.412 2.348,29.62 3.256,29.62 4.164,29.62 5.072,29.62 5.98,29.62 6.888,29.62 7.796,29.62 8.704,29.62 9.612,29.62 10.52,29.62 11.428,29.62 12.336,29.62 13.244,29.62 14.152,29.62 15.06,29.62 15.968,29.62 16.876,29.62 17.784,29.62 18.692,29.62 19.6,29.62 20.508,29.62 21.416,29.62 22.324,29.62 23.232,29.62 24.14,29.62 25.048,29.62 25.956,29.62 26.864,29.62 27.772,29.62 28.68,29.62 29.588,29.62 30.496,29.62 31.404,29.62 32.312,29.62 33.22,29.62 34.128,29.62 35.036,29.62 35.944,29.62 36.852,29.62 37.76,29.62 38.668,29.62 39.576,29.62 40.484,29.62 42.3,29.653 1.45,29.75 41.67,29.795 0.986,30.28 1.894,30.28 2.802,30.28 3.71,30.28 4.618,30.28 5.526,30.28 6.434,30.28 7.342,30.28 8.25,30.28 9.158,30.28 10.066,30.28 10.974,30.28 11.882,30.28 12.79,30.28 13.698,30.28 14.606,30.28 15.514,30.28 16.422,30.28 17.33,30.28 18.238,30.28 19.146,30.28 20.054,30.28 20.962,30.28 21.87,30.28 22.778,30.28 23.686,30.28 24.594,30.28 25.502,30.28 26.41,30.28 27.318,30.28 28.226,30.28 29.134,30.28 30.042,30.28 30.95,30.28 31.858,30.28 32.766,30.28 33.674,30.28 34.582,30.28 35.49,30.28 36.398,30.28 37.306,30.28 38.214,30.28 39.122,30.28 40.03,30.28 40.938,30.28 42.3,30.275
MATCHING_CELL_1: C14.2 C16.2 L3.2 L4.1 | length 2
  Top Layer w0.15: L3.2@29.884,15.168 29.825,15.226 29.825,15.773 C14.2@29.884,15.832
  Top Layer w0.4: 30.05,15.5 C16.2@30.725,15.5 L4.1@31.375,15.5
MATCHING_CELL_2: C3.1 C17.2 L4.2 | length 1.4
  Top Layer w0.4: L4.2@32.025,15.499 C17.2@32.675,15.5 C3.1@33.45,15.501
NetL1_2: L1.2 L2.1 | length 3.4
  Top Layer w0.3: L1.2@20.85,13.475 21.125,13.2 21.475,13.2 21.95,12.725 L2.1@23.975,12.725
PA0: CN1.3 U1.L7 | length 13.4
  Top Layer w0.1: U1.L7@26.992,16.199 27.696,16.903
  Top Layer w0.15: 27.696,16.903 27.696,16.95 28,17.254 28,18 28.336,18.336 28.944,18.336 29.159,18.55 v1(29.225,18.55)
  Signal Layer 1 w0.15: CN1.3@28.845,27.5 29.005,27.34 29.005,26.425 30.025,25.405 30.025,19.35 v1(29.225,18.55)
PA1: CN1.5 U1.J7 | length 14.1
  Top Layer w0.1: U1.J7@26.596,16.189 26.596,16.357 27.142,16.903
  Top Layer w0.15: 27.142,16.903 27.646,17.407 27.646,19.546 28.302,20.202 v1(28.334,20.202)
  Signal Layer 1 w0.15: CN1.5@23.65,27.6 23.875,27.375 23.875,26.425 25.75,24.55 25.75,23.732 28.334,21.148 v1(28.334,20.202)
PA2: CN1.7 U1.F7 | length 17.2
  Top Layer w0.1: U1.F7@25.963,16.199 25.963,16.624 26.287,16.948
  Top Layer w0.15: 26.287,16.948 26.287,19.587 27.39,20.69 27.39,20.929 v1(27.421,20.96)
  Signal Layer 1 w0.15: CN1.7@18.685,27.5 18.685,27.155 22.84,23 25.775,23 27.421,21.354 v1(27.421,20.96)
PA3: CN1.10 U1.G6 | length 23.7
  Top Layer w0.1: U1.G6@26.163,15.852 26.163,15.872 26.277,15.986 26.277,16.49 26.689,16.903
  Top Layer w0.15: 26.689,16.903 27.212,17.426 v1(27.212,17.632)
  Signal Layer 1 w0.15: CN1.10@10.9,27.25 11.315,27.25 13.215,25.35 16.858,25.35 20.033,22.175 24.65,22.175 27.212,19.613 v1(27.212,17.632)
PA8: CN1.4 U1.N7 | length 13.8
  Top Layer w0.1: U1.N7@27.392,16.199 27.611,16.199 27.774,16.362
  Top Layer w0.15: 27.774,16.362 28.665,17.253 v1(28.719,17.253)
  Signal Layer 1 w0.15: CN1.4@26.305,27.5 26.305,27.265 29.663,23.906 29.663,20.263 28.75,19.35 28.75,17.284 v1(28.719,17.253)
